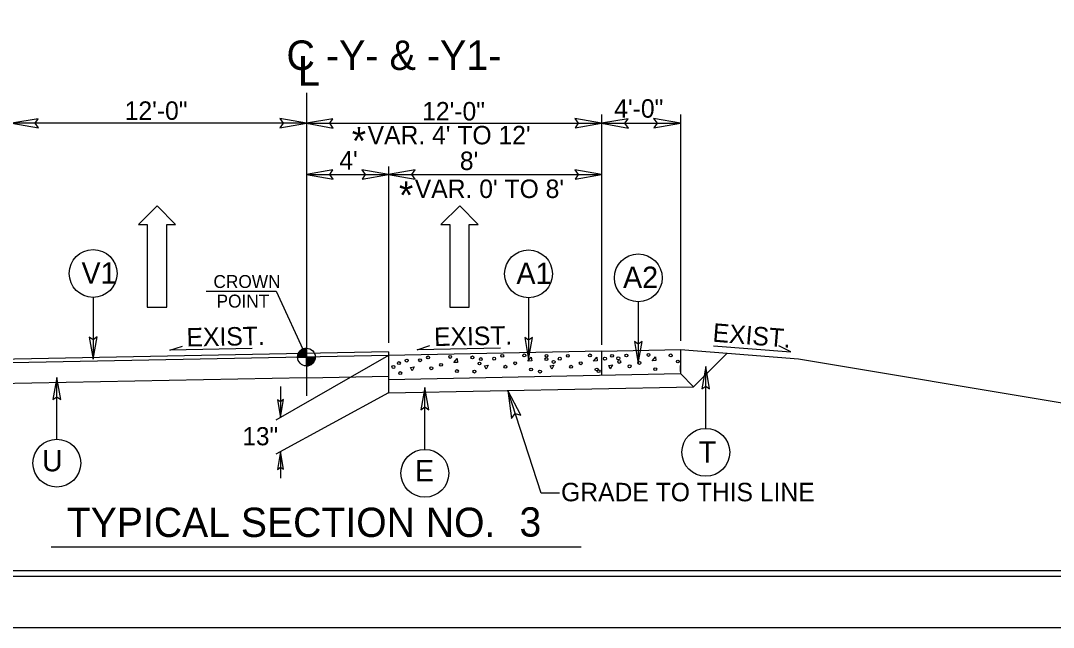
# Model space of a CAD drawing. Extents: x 2137858 to 2138172, y 2136084 to 2136289.
# Drawn here: x 2137980.7 to 2138065.4, y 2136083.7 to 2136133.4 of the extents above; entities that cross this region are included whole.
import ezdxf

# ---------------------------------------------------------------- set-up
doc = ezdxf.new("R2010")
doc.units = 0
for name, color, linetype in [('Old_Level_1', 7, 'Continuous'), ('Old_Level_11', 7, 'Continuous'), ('Old_Level_2', 7, 'Continuous'), ('Old_Level_20', 7, 'Continuous'), ('Old_Level_3', 7, 'Continuous'), ('Old_Level_4', 7, 'Continuous'), ('Sheet Cutting Line CELL', 7, 'Continuous'), ('Sheet Plot Border Inside CELL', 7, 'Continuous'), ('Sheet Plot Border Outside CELL', 7, 'Continuous'), ('Sheet Typical CELL', 7, 'Continuous'), ('Typical Grade Point Symbol CELL', 7, 'Continuous'), ('Typical Terminator CELL', 7, 'Continuous')]:
    doc.layers.add(name, color=color, linetype=linetype)

msp = doc.modelspace()

# ---------------------------------------------------------------- linework, layer by layer
at = {"layer": 'Old_Level_1'}
for p, q in [((2138037.543, 2136106.752), (2138043.891, 2136106.245)), ((2138043.891, 2136106.245), (2138042.905, 2136106.738)), ((2138010.907, 2136106.254), (2137973.562, 2136105.509)), ((2138010.907, 2136105.958), (2137980.015, 2136105.341)), ((2138010.907, 2136106.254), (2138010.907, 2136102.888)), ((2138038.646, 2136106.131), (2138044.502, 2136105.663)), ((2138044.502, 2136105.663), (2138066.282, 2136102.033)), ((2138004.169, 2136104.128), (2137973.562, 2136103.518)), ((2138004.169, 2136104.128), (2138010.907, 2136104.263)), ((2137983.242, 2136090.274), (2138026.684, 2136090.274))]:
    msp.add_line(p, q, dxfattribs=at)
for points in [[(2137999.732, 2136106.52), (2137992.967, 2136106.379), (2137994.005, 2136106.726)], [(2138020.086, 2136106.562), (2138013.259, 2136106.42), (2138014.297, 2136106.767)]]:
    msp.add_lwpolyline(points, dxfattribs=at)
at = {"layer": 'Old_Level_11'}
for p, q in [((2138004.169, 2136127.465), (2138004.169, 2136124.285)), ((2138004.169, 2136124.98), (2137980.015, 2136124.98)), ((2138004.169, 2136125.177), (2138004.169, 2136102.637)), ((2138004.169, 2136124.978), (2138028.369, 2136124.978)), ((2138028.369, 2136125.702), (2138028.369, 2136106.815)), ((2138028.369, 2136124.978), (2138034.822, 2136124.978)), ((2138034.822, 2136125.702), (2138034.822, 2136107.155)), ((2138004.169, 2136120.784), (2138010.907, 2136120.784)), ((2138010.907, 2136121.447), (2138010.907, 2136106.999)), ((2138010.907, 2136120.784), (2138028.369, 2136120.784)), ((2137986.686, 2136110.708), (2137986.686, 2136105.642)), ((2138022.377, 2136110.676), (2138022.377, 2136105.61)), ((2138031.37, 2136110.349), (2138031.37, 2136105.283)), ((2138028.369, 2136106.308), (2138028.369, 2136104.306)), ((2138034.822, 2136106.437), (2138034.822, 2136104.472)), ((2138010.907, 2136105.958), (2138001.65, 2136100.659)), ((2138036.907, 2136099.977), (2138036.907, 2136105.043)), ((2137983.714, 2136099.088), (2137983.714, 2136104.154)), ((2138010.907, 2136102.888), (2138001.65, 2136097.858)), ((2138002.045, 2136103.407), (2138002.045, 2136100.874)), ((2138013.885, 2136098.257), (2138013.885, 2136103.323)), ((2138023.409, 2136094.666), (2138020.671, 2136103.084)), ((2138002.045, 2136098.073), (2138002.045, 2136095.899)), ((2138024.927, 2136094.666), (2138023.409, 2136094.666))]:
    msp.add_line(p, q, dxfattribs=at)
for points in [[(2137982.193, 2136125.354), (2137980.015, 2136124.98), (2137982.206, 2136124.592), (2137981.927, 2136124.98)], [(2138001.991, 2136124.605), (2138004.169, 2136124.98), (2138001.978, 2136125.367), (2138002.257, 2136124.98)], [(2138006.347, 2136125.354), (2138004.169, 2136124.978), (2138006.358, 2136124.591), (2138006.08, 2136124.978)], [(2138026.191, 2136124.602), (2138028.369, 2136124.978), (2138026.179, 2136125.365), (2138026.457, 2136124.978)], [(2138030.547, 2136125.354), (2138028.369, 2136124.978), (2138030.56, 2136124.591), (2138030.28, 2136124.978)], [(2138032.644, 2136124.602), (2138034.822, 2136124.978), (2138032.631, 2136125.365), (2138032.91, 2136124.978)], [(2138006.347, 2136121.16), (2138004.169, 2136120.784), (2138006.358, 2136120.397), (2138006.08, 2136120.784)], [(2138008.729, 2136120.41), (2138010.907, 2136120.784), (2138008.716, 2136121.171), (2138008.995, 2136120.784)], [(2138013.085, 2136121.16), (2138010.907, 2136120.784), (2138013.096, 2136120.397), (2138012.819, 2136120.784)], [(2138026.191, 2136120.41), (2138028.369, 2136120.784), (2138026.178, 2136121.171), (2138026.457, 2136120.784)], [(2137986.373, 2136107.457), (2137986.686, 2136105.642), (2137987.009, 2136107.467), (2137986.686, 2136107.236)], [(2138022.064, 2136107.425), (2138022.377, 2136105.61), (2138022.7, 2136107.434), (2138022.377, 2136107.204)], [(2138031.057, 2136107.098), (2138031.37, 2136105.283), (2138031.693, 2136107.108), (2138031.37, 2136106.877)], [(2138037.22, 2136103.228), (2138036.907, 2136105.043), (2138036.584, 2136103.218), (2138036.907, 2136103.449)], [(2137984.027, 2136102.339), (2137983.714, 2136104.154), (2137983.391, 2136102.33), (2137983.714, 2136102.56)], [(2138014.198, 2136101.508), (2138013.885, 2136103.323), (2138013.562, 2136101.498), (2138013.885, 2136101.729)], [(2138001.795, 2136102.325), (2138002.045, 2136100.873), (2138002.303, 2136102.333), (2138002.045, 2136102.148)], [(2138002.295, 2136096.621), (2138002.045, 2136098.073), (2138001.787, 2136096.613), (2138002.045, 2136096.798)]]:
    msp.add_lwpolyline(points, close=True, dxfattribs=at)
for centre in [(2137986.687, 2136112.67), (2138022.378, 2136112.637), (2138031.371, 2136112.31), (2138036.905, 2136098.016), (2137983.712, 2136097.128), (2138013.883, 2136096.296)]:
    msp.add_circle(centre, 1.96, dxfattribs=at)
at = {"layer": 'Old_Level_2'}
for p, q in [((2138028.369, 2136106.308), (2138010.907, 2136105.958)), ((2138028.369, 2136106.308), (2138034.822, 2136106.437)), ((2138034.822, 2136106.437), (2138038.646, 2136106.131)), ((2138004.178, 2136105.33), (2138004.169, 2136105.823)), ((2138038.646, 2136106.131), (2138035.904, 2136103.39)), ((2138034.822, 2136104.639), (2138034.822, 2136105.132)), ((2138010.907, 2136103.993), (2138034.822, 2136104.472)), ((2138034.822, 2136104.472), (2138035.904, 2136103.39)), ((2138010.907, 2136102.888), (2138035.904, 2136103.39))]:
    msp.add_line(p, q, dxfattribs=at)
at = {"layer": 'Old_Level_3'}
for p, q in [((2137995.958, 2136111.228), (2138001.697, 2136111.228)), ((2138001.697, 2136111.228), (2138004.169, 2136105.823))]:
    msp.add_line(p, q, dxfattribs=at)
for points in [[(2138016.561, 2136105.387), (2138016.257, 2136105.363), (2138016.521, 2136105.691)], [(2138022.637, 2136105.515), (2138022.333, 2136105.49), (2138022.596, 2136105.818)], [(2138028.014, 2136105.515), (2138027.71, 2136105.49), (2138027.974, 2136105.818)], [(2138032.815, 2136105.546), (2138032.511, 2136105.522), (2138032.774, 2136105.849)], [(2138013.002, 2136105.026), (2138012.826, 2136104.694), (2138012.701, 2136104.971)], [(2138019.078, 2136105.153), (2138018.902, 2136104.821), (2138018.777, 2136105.098)], [(2138024.455, 2136105.153), (2138024.279, 2136104.821), (2138024.154, 2136105.098)], [(2138029.256, 2136105.185), (2138029.079, 2136104.853), (2138028.955, 2136105.13)]]:
    msp.add_lwpolyline(points, close=True, dxfattribs=at)
for centre in [(2138011.754, 2136105.328), (2138012.39, 2136105.528), (2138013.483, 2136105.56), (2138014.144, 2136105.792), (2138015.956, 2136105.833), (2138017.774, 2136105.795), (2138018.466, 2136105.655), (2138019.559, 2136105.687), (2138020.22, 2136105.919), (2138021.283, 2136105.311), (2138022.032, 2136105.96), (2138023.844, 2136105.655), (2138023.85, 2136105.922), (2138024.437, 2136105.424), (2138024.936, 2136105.687), (2138025.597, 2136105.919), (2138026.66, 2136105.311), (2138027.409, 2136105.96), (2138028.644, 2136105.687), (2138029.228, 2136105.922), (2138029.737, 2136105.718), (2138029.814, 2136105.424), (2138030.397, 2136105.951), (2138031.46, 2136105.343), (2138032.21, 2136105.992), (2138034.028, 2136105.954), (2138034.614, 2136105.455), (2138011.299, 2136105.008), (2138011.864, 2136104.505), (2138014.408, 2136104.904), (2138015.207, 2136105.184), (2138016.511, 2136104.673), (2138017.94, 2136104.632), (2138018.361, 2136105.297), (2138020.484, 2136105.031), (2138022.587, 2136104.8), (2138023.317, 2136104.632), (2138025.861, 2136105.031), (2138027.964, 2136104.8), (2138028.118, 2136104.664), (2138030.661, 2136105.063), (2138032.765, 2136104.832)]:
    msp.add_circle(centre, 0.119, dxfattribs=at)
at = {"layer": 'Old_Level_4'}
for p, q in [((2137991.947, 2136118.212), (2137990.398, 2136116.687)), ((2137993.447, 2136116.687), (2137991.947, 2136118.212)), ((2138016.743, 2136118.212), (2138015.194, 2136116.687)), ((2138018.243, 2136116.687), (2138016.743, 2136118.212)), ((2137990.398, 2136116.687), (2137991.124, 2136116.687)), ((2137991.124, 2136116.687), (2137991.124, 2136109.911)), ((2137992.721, 2136109.911), (2137992.721, 2136116.687)), ((2137992.721, 2136116.687), (2137993.447, 2136116.687)), ((2138015.194, 2136116.687), (2138015.92, 2136116.687)), ((2138015.92, 2136116.687), (2138015.92, 2136109.911)), ((2138017.517, 2136109.911), (2138017.517, 2136116.687)), ((2138017.517, 2136116.687), (2138018.243, 2136116.687)), ((2137991.124, 2136109.911), (2137992.721, 2136109.911)), ((2138015.92, 2136109.911), (2138017.517, 2136109.911))]:
    msp.add_line(p, q, dxfattribs=at)
at = {"layer": 'Sheet Cutting Line CELL'}
msp.add_line((2137858.136, 2136083.673), (2138172.482, 2136083.673), dxfattribs=at)
at = {"layer": 'Sheet Plot Border Inside CELL'}
msp.add_lwpolyline([(2138171.642, 2136284.815), (2137860.562, 2136284.815), (2137860.562, 2136087.863), (2138171.642, 2136087.863)], close=True, dxfattribs=at)
at = {"layer": 'Sheet Plot Border Outside CELL'}
msp.add_lwpolyline([(2138172.482, 2136289.006), (2137858.136, 2136289.006), (2137858.136, 2136083.673), (2138172.482, 2136083.673)], close=True, dxfattribs=at)
at = {"layer": 'Sheet Typical CELL'}
msp.add_lwpolyline([(2138169.309, 2136284.339), (2137889.309, 2136284.339), (2137889.309, 2136088.339), (2138169.309, 2136088.339)], close=True, dxfattribs=at)
at = {"layer": 'Typical Grade Point Symbol CELL'}
for p, q in [((2138004.169, 2136105.823), (2138004.169, 2136106.549)), ((2138003.443, 2136105.823), (2138004.169, 2136105.823)), ((2138004.17, 2136105.097), (2138004.169, 2136105.823)), ((2138004.895, 2136105.823), (2138004.169, 2136105.823)), ((2138004.169, 2136105.823), (2138004.17, 2136105.097))]:
    msp.add_line(p, q, dxfattribs=at)
for points in [[(2138003.596, 2136106.269), (2138003.596, 2136105.823)], [(2138003.61, 2136106.286), (2138003.61, 2136105.823)], [(2138003.625, 2136106.304), (2138003.625, 2136105.823)], [(2138003.639, 2136106.32), (2138003.639, 2136105.823)], [(2138003.654, 2136106.335), (2138003.654, 2136105.823)], [(2138003.669, 2136106.349), (2138003.669, 2136105.823)], [(2138003.683, 2136106.362), (2138003.683, 2136105.823)], [(2138003.698, 2136106.375), (2138003.698, 2136105.823)], [(2138003.712, 2136106.388), (2138003.712, 2136105.823)], [(2138003.727, 2136106.399), (2138003.727, 2136105.823)], [(2138003.741, 2136106.409), (2138003.741, 2136105.823)], [(2138003.756, 2136106.42), (2138003.756, 2136105.823)], [(2138003.77, 2136106.43), (2138003.77, 2136105.823)], [(2138003.785, 2136106.44), (2138003.785, 2136105.823)], [(2138003.799, 2136106.448), (2138003.799, 2136105.823)], [(2138003.814, 2136106.456), (2138003.814, 2136105.823)], [(2138003.828, 2136106.464), (2138003.828, 2136105.823)], [(2138003.843, 2136106.472), (2138003.843, 2136105.823)], [(2138003.857, 2136106.478), (2138003.857, 2136105.823)], [(2138003.872, 2136106.485), (2138003.872, 2136105.823)], [(2138003.886, 2136106.491), (2138003.886, 2136105.823)], [(2138003.901, 2136106.498), (2138003.901, 2136105.823)], [(2138003.915, 2136106.504), (2138003.915, 2136105.823)], [(2138003.93, 2136106.509), (2138003.93, 2136105.823)], [(2138003.944, 2136106.514), (2138003.944, 2136105.823)], [(2138003.959, 2136106.519), (2138003.959, 2136105.823)], [(2138003.973, 2136106.522), (2138003.973, 2136105.823)], [(2138003.988, 2136106.527), (2138003.988, 2136105.823)], [(2138004.002, 2136106.53), (2138004.002, 2136105.823)], [(2138004.017, 2136106.533), (2138004.017, 2136105.823)], [(2138004.032, 2136106.536), (2138004.032, 2136105.823)], [(2138004.046, 2136106.54), (2138004.046, 2136105.823)], [(2138004.061, 2136106.541), (2138004.061, 2136105.823)], [(2138004.075, 2136106.543), (2138004.075, 2136105.823)], [(2138004.09, 2136106.544), (2138004.09, 2136105.823)], [(2138004.104, 2136106.546), (2138004.104, 2136105.823)], [(2138004.119, 2136106.548), (2138004.119, 2136105.823)], [(2138004.133, 2136106.548), (2138004.133, 2136105.823)], [(2138004.148, 2136106.549), (2138004.148, 2136105.823)], [(2138004.162, 2136106.549), (2138004.162, 2136106.549), (2138004.162, 2136105.823)], [(2138003.451, 2136105.927), (2138003.451, 2136105.823)], [(2138003.465, 2136106.001), (2138003.465, 2136105.823)], [(2138003.48, 2136106.051), (2138003.48, 2136105.823)], [(2138003.494, 2136106.091), (2138003.494, 2136105.823)], [(2138003.509, 2136106.125), (2138003.509, 2136105.823)], [(2138003.523, 2136106.156), (2138003.523, 2136105.823)], [(2138003.538, 2136106.181), (2138003.538, 2136105.823)], [(2138003.552, 2136106.206), (2138003.552, 2136105.823)], [(2138003.567, 2136106.228), (2138003.567, 2136105.823)], [(2138003.581, 2136106.249), (2138003.581, 2136105.823)], [(2138004.18, 2136105.823), (2138004.18, 2136105.097), (2138004.18, 2136105.097)], [(2138004.194, 2136105.823), (2138004.194, 2136105.097)], [(2138004.209, 2136105.823), (2138004.209, 2136105.099)], [(2138004.224, 2136105.823), (2138004.224, 2136105.099)], [(2138004.238, 2136105.823), (2138004.238, 2136105.101)], [(2138004.253, 2136105.823), (2138004.253, 2136105.102)], [(2138004.267, 2136105.823), (2138004.267, 2136105.104)], [(2138004.282, 2136105.823), (2138004.282, 2136105.107)], [(2138004.296, 2136105.823), (2138004.296, 2136105.109)], [(2138004.311, 2136105.823), (2138004.311, 2136105.112)], [(2138004.325, 2136105.823), (2138004.325, 2136105.115)], [(2138004.34, 2136105.823), (2138004.34, 2136105.118)], [(2138004.354, 2136105.823), (2138004.354, 2136105.121)], [(2138004.369, 2136105.823), (2138004.369, 2136105.126)], [(2138004.383, 2136105.823), (2138004.383, 2136105.13)], [(2138004.398, 2136105.823), (2138004.398, 2136105.134)], [(2138004.412, 2136105.823), (2138004.412, 2136105.139)], [(2138004.427, 2136105.823), (2138004.427, 2136105.144)], [(2138004.441, 2136105.823), (2138004.441, 2136105.151)], [(2138004.456, 2136105.823), (2138004.456, 2136105.157)], [(2138004.47, 2136105.823), (2138004.47, 2136105.163)], [(2138004.485, 2136105.823), (2138004.485, 2136105.17)], [(2138004.499, 2136105.823), (2138004.499, 2136105.176)], [(2138004.514, 2136105.823), (2138004.514, 2136105.184)], [(2138004.528, 2136105.823), (2138004.528, 2136105.192)], [(2138004.543, 2136105.823), (2138004.543, 2136105.201)], [(2138004.557, 2136105.823), (2138004.557, 2136105.21)], [(2138004.572, 2136105.823), (2138004.572, 2136105.22)], [(2138004.587, 2136105.823), (2138004.587, 2136105.23)], [(2138004.601, 2136105.823), (2138004.601, 2136105.239)], [(2138004.616, 2136105.823), (2138004.616, 2136105.251)], [(2138004.63, 2136105.823), (2138004.63, 2136105.262)], [(2138004.645, 2136105.823), (2138004.645, 2136105.275)], [(2138004.659, 2136105.823), (2138004.659, 2136105.288)], [(2138004.674, 2136105.823), (2138004.674, 2136105.301)], [(2138004.688, 2136105.823), (2138004.688, 2136105.315)], [(2138004.703, 2136105.823), (2138004.703, 2136105.331)], [(2138004.717, 2136105.823), (2138004.717, 2136105.347)], [(2138004.732, 2136105.823), (2138004.732, 2136105.365)], [(2138004.746, 2136105.823), (2138004.746, 2136105.383)], [(2138004.761, 2136105.823), (2138004.761, 2136105.402)], [(2138004.775, 2136105.823), (2138004.775, 2136105.423)], [(2138004.79, 2136105.823), (2138004.79, 2136105.446)], [(2138004.804, 2136105.823), (2138004.804, 2136105.472)], [(2138004.819, 2136105.823), (2138004.819, 2136105.499)], [(2138004.833, 2136105.823), (2138004.833, 2136105.53)], [(2138004.848, 2136105.823), (2138004.848, 2136105.564)], [(2138004.862, 2136105.823), (2138004.862, 2136105.607)], [(2138004.877, 2136105.823), (2138004.877, 2136105.659)], [(2138004.891, 2136105.823), (2138004.891, 2136105.744)]]:
    msp.add_lwpolyline(points, dxfattribs=at)
msp.add_circle((2138004.17, 2136105.824), 0.726, dxfattribs=at)
for start, end in [(90.00952, 180.00952), (270.00952, 0.00952)]:
    msp.add_arc((2138004.17, 2136105.824), 0.726, start, end, dxfattribs=at)
at = {"layer": 'Typical Terminator CELL'}
msp.add_lwpolyline([(2138021.744, 2136101.048), (2138020.671, 2136103.084), (2138020.993, 2136100.79), (2138021.287, 2136101.191)], close=True, dxfattribs=at)

# ---------------------------------------------------------------- texts
at = {"layer": 'Old_Level_1'}
for s, height, p in [('12\'-0"', 1.5125, (2137989.274, 2136125.259)), ('12\'-0"', 1.5125, (2138013.656, 2136125.209)), ('4\'-0"', 1.5125, (2138029.402, 2136125.435)), ('*', 2.25, (2138007.891, 2136122.415)), ("VAR. 4' TO 12'", 1.5125, (2138009.186, 2136123.252)), ("4'", 1.5125, (2138006.867, 2136121.181)), ("  8'", 1.5125, (2138015.624, 2136121.147)), ('*', 2.25, (2138011.755, 2136117.965)), ("VAR. 0' TO 8'", 1.5125, (2138013.054, 2136118.855))]:
    msp.add_text(s, height=height, dxfattribs=at).set_placement(p)
for rotation, p in [(1.19158, (2137994.358, 2136106.682)), (1.19158, (2138014.65, 2136106.722)), (355.42832, (2138037.43, 2136107.09))]:
    msp.add_text('EXIST.', height=1.5125, rotation=rotation, dxfattribs=at).set_placement(p)
at = {"layer": 'Old_Level_11'}
for s, height, p in [('CROWN', 1.0583, (2137996.549, 2136111.481)), ('POINT', 1.0583, (2137996.804, 2136109.878)), ('13"', 1.4887, (2137998.928, 2136098.591))]:
    msp.add_text(s, height=height, dxfattribs=at).set_placement(p)
at = {"layer": 'Old_Level_20'}
for s, height, p in [('V1', 1.7545, (2137985.735, 2136111.839)), ('A1', 1.7545, (2138021.386, 2136111.807)), ('A2', 1.7545, (2138030.127, 2136111.48)), ('T', 1.754, (2138036.329, 2136097.161)), ('U', 1.754, (2137982.498, 2136096.457)), ('E', 1.754, (2138013.069, 2136095.625))]:
    msp.add_text(s, height=height, dxfattribs=at).set_placement(p)
at = {"layer": 'Old_Level_3'}
for s, height, p in [('C -Y- & -Y1-', 2.42, (2138002.534, 2136129.347)), ('L', 2.42, (2138003.474, 2136128.067)), ('GRADE TO THIS LINE', 1.5125, (2138025.044, 2136094.003)), ('TYPICAL SECTION NO.  ', 2.4, (2137984.53, 2136091.078)), ('3', 2.4, (2138021.634, 2136091.11))]:
    msp.add_text(s, height=height, dxfattribs=at).set_placement(p)

doc.saveas('drawing.dxf')
